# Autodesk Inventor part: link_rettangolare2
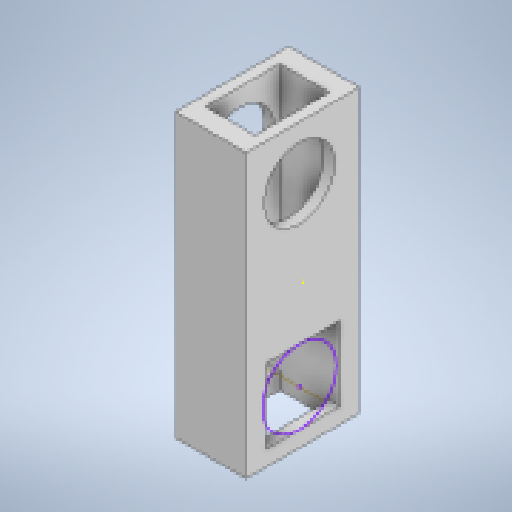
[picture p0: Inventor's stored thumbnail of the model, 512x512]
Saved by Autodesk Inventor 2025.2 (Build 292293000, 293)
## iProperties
Created: 2025-06
Part Number: link_rettangolare2
Material: Generico
Document SubType Name: Modeling
Designer: 18907419
Density: 1 g/cm^3
Appearance: Default
Author: 18907419
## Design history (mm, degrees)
sketch "Schizzo3"
  geometry: L1 (-20, 80)-(20, 80); L2 (20, 80)-(20, -80); L3 (20, -80)-(-20, -80); L4 (-20, -80)-(-20, 80); L5 (-20, 80)-(20, -80); L6 (20, 80)-(-20, -80); 1 further point
  constraints: 12 end point, 2 midpoint, 2 parallel, 1 horizontal, 1 perpendicular
  dimensions: "d9" = 40 distance of L2.end L3.end; "d10" = 160 distance of L1.end L2.end
extrude "Estrusione3" new body sketch "Schizzo3" stored distance "d11" = 64; taper "d12" = 0 deg
sketch "Schizzo4"
  geometry: L1 (7, 11)-(33, 11); L2 (33, 11)-(33, 53); L3 (33, 53)-(7, 53); L4 (7, 53)-(7, 11); L5 (7, 11)-(33, 53); L6 (33, 11)-(7, 53); 1 further point
  constraints: 12 end point, 2 midpoint, 2 parallel, 1 horizontal, 1 perpendicular
  dimensions: "d13" = 26 distance of L3.end L2.end; "d14" = 42 distance of L2.end L1.end
extrude "Estrusione4" cut sketch "Schizzo4" extent not by distance; stored distance "d15" = 0; taper "d16" = 0 deg
sketch "Schizzo5"
  geometry: L1 (64, 0)-(0, 0) reference; L2 (32, 0)-(32, 30); L3 (11, 51)-(53, 51); L4 (53, 51)-(53, 9); L5 (53, 9)-(11, 9); L6 (11, 9)-(11, 51); L7 (11, 51)-(53, 9); L8 (53, 51)-(11, 9); 1 further point
  constraints: 14 end point, 3 midpoint, 2 parallel, 1 horizontal, 1 perpendicular, 1 vertical
  dimensions: "d17" = 30 distance of L2.start L2.end; "d18" = 42 distance of L4.end L5.end; "d19" = 42 distance of L3.end L4.end
extrude "Estrusione5" cut sketch "Schizzo5" extent not by distance; stored distance "d20" = 0; taper "d21" = 0 deg
sketch "Schizzo6"
  geometry: C1 r 21 at (30, 30); 1 further point
  constraints: 1 centre point
node "Asse di lavoro1"
sketch "Schizzo7"
  geometry: L1 (30, 30)-(30, 130); C1 r 21 at (30, 30) reference; C2 r 20 at (30, 130); 1 further point
  constraints: 2 end point, 1 centre point, 1 coincident, 1 vertical
  dimensions: "d22" = 100 distance of L1.start L1.end; "d23" = 40 diameter of C2
extrude "Estrusione6" cut sketch "Schizzo7" extent not by distance; stored distance "d24" = 0; taper "d25" = 0 deg
sketch "Schizzo10"
  geometry: L1 (11, 9)-(11, 51) reference; L2 (11, 51)-(53, 51) reference; L3 (53, 51)-(53, 9) reference; L4 (53, 9)-(11, 9) reference; L5 (64, 160)-(0, 160) reference; L6 (0, 0)-(0, 160) reference; L7 (64, 0)-(0, 0) reference; L8 (64, 160)-(64, 0) reference; C1 r 20 at (30, 130) reference; C2 r 7.5 at (30, 30); 1 further point
  constraints: 1 centre point
  dimensions: "d30" = 15 diameter of C2
extrude "Estrusione9" join sketch "Schizzo10" stored distance "d31" = 64; taper "d32" = 0 deg
node "Solido2"
node "Linea chiusa proiettata2"
